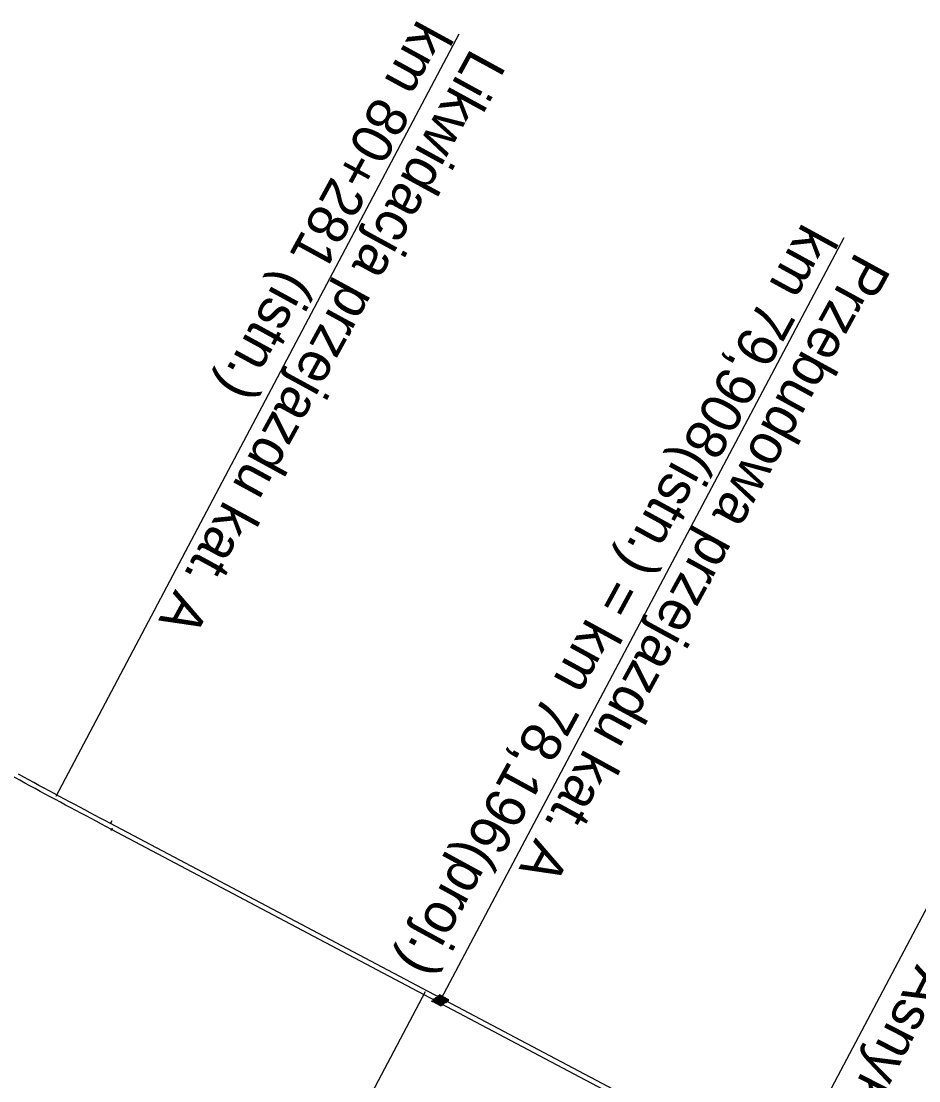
# Model space of a CAD drawing. Extents: x 6540402 to 6566579, y 5525343 to 5532423.
# Drawn here: x 6541266 to 6542041, y 5527285 to 5528200 of the extents above; entities that cross this region are included whole.
import ezdxf

# ---------------------------------------------------------------- set-up
doc = ezdxf.new("R2010")
doc.units = 0
for name, color, linetype in [('IR_ps_geometria', 7, 'Continuous'), ('TOR_PS_OPIS_T-opisy dodatkowe', 7, 'Continuous'), ('TOR_PS_OPIS_T-symbole geometrii', 7, 'Continuous'), ('TOR_PS_P-płyty przejazdowe', 7, 'Continuous'), ('TOR_PS_T-tory projektowane', 7, 'Continuous')]:
    doc.layers.add(name, color=color, linetype=linetype)

msp = doc.modelspace()

# ---------------------------------------------------------------- linework, layer by layer
at = {"layer": 'IR_ps_geometria'}
msp.add_lwpolyline([(6541344.09, 5527502.02), (6541343.97, 5527501.8), (6541344, 5527501.79), (6541344.03, 5527501.76), (6541344.05, 5527501.74), (6541344.07, 5527501.71), (6541344.09, 5527501.69), (6541344.1, 5527501.66), (6541344.1, 5527501.62), (6541344.11, 5527501.59), (6541344.11, 5527501.56), (6541344.1, 5527501.53), (6541344.09, 5527501.49), (6541344.08, 5527501.46), (6541344.06, 5527501.44), (6541344.04, 5527501.41), (6541344.02, 5527501.39), (6541343.99, 5527501.37), (6541343.96, 5527501.35), (6541343.93, 5527501.34), (6541343.9, 5527501.33), (6541343.87, 5527501.33), (6541343.83, 5527501.33), (6541343.8, 5527501.34), (6541343.77, 5527501.35), (6541343.74, 5527501.36), (6541343.71, 5527501.38), (6541343.69, 5527501.4), (6541343.67, 5527501.42), (6541343.65, 5527501.45), (6541343.63, 5527501.48), (6541343.62, 5527501.51), (6541343.61, 5527501.54), (6541343.61, 5527501.57), (6541343.61, 5527501.6), (6541343.61, 5527501.64), (6541343.62, 5527501.67), (6541343.64, 5527501.7), (6541343.65, 5527501.73), (6541343.67, 5527501.75), (6541343.7, 5527501.77), (6541343.73, 5527501.79), (6541343.75, 5527501.81), (6541343.78, 5527501.82), (6541343.82, 5527501.83), (6541343.85, 5527501.83), (6541343.88, 5527501.83), (6541343.91, 5527501.83), (6541343.95, 5527501.82), (6541343.97, 5527501.8), (6541344.21, 5527502.24), (6541344.18, 5527502.26), (6541344.16, 5527502.28), (6541344.13, 5527502.31), (6541344.11, 5527502.33), (6541344.1, 5527502.36), (6541344.09, 5527502.39), (6541344.08, 5527502.42), (6541344.08, 5527502.46), (6541344.08, 5527502.49), (6541344.08, 5527502.52), (6541344.09, 5527502.55), (6541344.1, 5527502.58), (6541344.12, 5527502.61), (6541344.14, 5527502.64), (6541344.17, 5527502.66), (6541344.19, 5527502.68), (6541344.22, 5527502.69), (6541344.25, 5527502.7), (6541344.28, 5527502.71), (6541344.32, 5527502.72), (6541344.35, 5527502.71), (6541344.38, 5527502.71), (6541344.41, 5527502.7), (6541344.44, 5527502.69), (6541344.47, 5527502.67), (6541344.5, 5527502.65), (6541344.52, 5527502.62), (6541344.54, 5527502.6), (6541344.55, 5527502.57), (6541344.56, 5527502.54), (6541344.57, 5527502.51), (6541344.58, 5527502.47), (6541344.57, 5527502.44), (6541344.57, 5527502.41), (6541344.56, 5527502.38), (6541344.55, 5527502.35), (6541344.53, 5527502.32), (6541344.51, 5527502.3), (6541344.48, 5527502.27), (6541344.46, 5527502.25), (6541344.43, 5527502.24), (6541344.4, 5527502.23), (6541344.37, 5527502.22), (6541344.33, 5527502.22), (6541344.3, 5527502.22), (6541344.27, 5527502.22), (6541344.24, 5527502.23), (6541344.21, 5527502.24)], close=True, dxfattribs=at)
msp.add_lwpolyline([(6541344.09, 5527502.02), (6541343.97, 5527501.8), (6541344, 5527501.79), (6541344.03, 5527501.76), (6541344.05, 5527501.74), (6541344.07, 5527501.71), (6541344.09, 5527501.69), (6541344.1, 5527501.66), (6541344.1, 5527501.62), (6541344.11, 5527501.59), (6541344.11, 5527501.56), (6541344.1, 5527501.53), (6541344.09, 5527501.49), (6541344.08, 5527501.46), (6541344.06, 5527501.44), (6541344.04, 5527501.41), (6541344.02, 5527501.39), (6541343.99, 5527501.37), (6541343.96, 5527501.35), (6541343.93, 5527501.34), (6541343.9, 5527501.33), (6541343.87, 5527501.33), (6541343.83, 5527501.33), (6541343.8, 5527501.34), (6541343.77, 5527501.35), (6541343.74, 5527501.36), (6541343.71, 5527501.38), (6541343.69, 5527501.4), (6541343.67, 5527501.42), (6541343.65, 5527501.45), (6541343.63, 5527501.48), (6541343.62, 5527501.51), (6541343.61, 5527501.54), (6541343.61, 5527501.57), (6541343.61, 5527501.6), (6541343.61, 5527501.64), (6541343.62, 5527501.67), (6541343.64, 5527501.7), (6541343.65, 5527501.73), (6541343.67, 5527501.75), (6541343.7, 5527501.77), (6541343.73, 5527501.79), (6541343.75, 5527501.81), (6541343.78, 5527501.82), (6541343.82, 5527501.83), (6541343.85, 5527501.83), (6541343.88, 5527501.83), (6541343.91, 5527501.83), (6541343.95, 5527501.82), (6541343.97, 5527501.8), (6541344.21, 5527502.24), (6541344.18, 5527502.26), (6541344.16, 5527502.28), (6541344.13, 5527502.31), (6541344.11, 5527502.33), (6541344.1, 5527502.36), (6541344.09, 5527502.39), (6541344.08, 5527502.42), (6541344.08, 5527502.46), (6541344.08, 5527502.49), (6541344.08, 5527502.52), (6541344.09, 5527502.55), (6541344.1, 5527502.58), (6541344.12, 5527502.61), (6541344.14, 5527502.64), (6541344.17, 5527502.66), (6541344.19, 5527502.68), (6541344.22, 5527502.69), (6541344.25, 5527502.7), (6541344.28, 5527502.71), (6541344.32, 5527502.72), (6541344.35, 5527502.71), (6541344.38, 5527502.71), (6541344.41, 5527502.7), (6541344.44, 5527502.69), (6541344.47, 5527502.67), (6541344.5, 5527502.65), (6541344.52, 5527502.62), (6541344.54, 5527502.6), (6541344.55, 5527502.57), (6541344.56, 5527502.54), (6541344.57, 5527502.51), (6541344.58, 5527502.47), (6541344.57, 5527502.44), (6541344.57, 5527502.41), (6541344.56, 5527502.38), (6541344.55, 5527502.35), (6541344.53, 5527502.32), (6541344.51, 5527502.3), (6541344.48, 5527502.27), (6541344.46, 5527502.25), (6541344.43, 5527502.24), (6541344.4, 5527502.23), (6541344.37, 5527502.22), (6541344.33, 5527502.22), (6541344.3, 5527502.22), (6541344.27, 5527502.22), (6541344.24, 5527502.23), (6541344.21, 5527502.24)], close=True, dxfattribs=at)
msp.add_lwpolyline([(6541344.09, 5527502.02), (6541343.97, 5527501.8), (6541344, 5527501.79), (6541344.03, 5527501.76), (6541344.05, 5527501.74), (6541344.07, 5527501.71), (6541344.09, 5527501.69), (6541344.1, 5527501.66), (6541344.1, 5527501.62), (6541344.11, 5527501.59), (6541344.11, 5527501.56), (6541344.1, 5527501.53), (6541344.09, 5527501.49), (6541344.08, 5527501.46), (6541344.06, 5527501.44), (6541344.04, 5527501.41), (6541344.02, 5527501.39), (6541343.99, 5527501.37), (6541343.96, 5527501.35), (6541343.93, 5527501.34), (6541343.9, 5527501.33), (6541343.87, 5527501.33), (6541343.83, 5527501.33), (6541343.8, 5527501.34), (6541343.77, 5527501.35), (6541343.74, 5527501.36), (6541343.71, 5527501.38), (6541343.69, 5527501.4), (6541343.67, 5527501.42), (6541343.65, 5527501.45), (6541343.63, 5527501.48), (6541343.62, 5527501.51), (6541343.61, 5527501.54), (6541343.61, 5527501.57), (6541343.61, 5527501.6), (6541343.61, 5527501.64), (6541343.62, 5527501.67), (6541343.64, 5527501.7), (6541343.65, 5527501.73), (6541343.67, 5527501.75), (6541343.7, 5527501.77), (6541343.73, 5527501.79), (6541343.75, 5527501.81), (6541343.78, 5527501.82), (6541343.82, 5527501.83), (6541343.85, 5527501.83), (6541343.88, 5527501.83), (6541343.91, 5527501.83), (6541343.95, 5527501.82), (6541343.97, 5527501.8), (6541344.21, 5527502.24), (6541344.18, 5527502.26), (6541344.16, 5527502.28), (6541344.13, 5527502.31), (6541344.11, 5527502.33), (6541344.1, 5527502.36), (6541344.09, 5527502.39), (6541344.08, 5527502.42), (6541344.08, 5527502.46), (6541344.08, 5527502.49), (6541344.08, 5527502.52), (6541344.09, 5527502.55), (6541344.1, 5527502.58), (6541344.12, 5527502.61), (6541344.14, 5527502.64), (6541344.17, 5527502.66), (6541344.19, 5527502.68), (6541344.22, 5527502.69), (6541344.25, 5527502.7), (6541344.28, 5527502.71), (6541344.32, 5527502.72), (6541344.35, 5527502.71), (6541344.38, 5527502.71), (6541344.41, 5527502.7), (6541344.44, 5527502.69), (6541344.47, 5527502.67), (6541344.5, 5527502.65), (6541344.52, 5527502.62), (6541344.54, 5527502.6), (6541344.55, 5527502.57), (6541344.56, 5527502.54), (6541344.57, 5527502.51), (6541344.58, 5527502.47), (6541344.57, 5527502.44), (6541344.57, 5527502.41), (6541344.56, 5527502.38), (6541344.55, 5527502.35), (6541344.53, 5527502.32), (6541344.51, 5527502.3), (6541344.48, 5527502.27), (6541344.46, 5527502.25), (6541344.43, 5527502.24), (6541344.4, 5527502.23), (6541344.37, 5527502.22), (6541344.33, 5527502.22), (6541344.3, 5527502.22), (6541344.27, 5527502.22), (6541344.24, 5527502.23), (6541344.21, 5527502.24)], close=True, dxfattribs=at)
msp.add_lwpolyline([(6541344.09, 5527502.02), (6541343.97, 5527501.8), (6541344, 5527501.79), (6541344.03, 5527501.76), (6541344.05, 5527501.74), (6541344.07, 5527501.71), (6541344.09, 5527501.69), (6541344.1, 5527501.66), (6541344.1, 5527501.62), (6541344.11, 5527501.59), (6541344.11, 5527501.56), (6541344.1, 5527501.53), (6541344.09, 5527501.49), (6541344.08, 5527501.46), (6541344.06, 5527501.44), (6541344.04, 5527501.41), (6541344.02, 5527501.39), (6541343.99, 5527501.37), (6541343.96, 5527501.35), (6541343.93, 5527501.34), (6541343.9, 5527501.33), (6541343.87, 5527501.33), (6541343.83, 5527501.33), (6541343.8, 5527501.34), (6541343.77, 5527501.35), (6541343.74, 5527501.36), (6541343.71, 5527501.38), (6541343.69, 5527501.4), (6541343.67, 5527501.42), (6541343.65, 5527501.45), (6541343.63, 5527501.48), (6541343.62, 5527501.51), (6541343.61, 5527501.54), (6541343.61, 5527501.57), (6541343.61, 5527501.6), (6541343.61, 5527501.64), (6541343.62, 5527501.67), (6541343.64, 5527501.7), (6541343.65, 5527501.73), (6541343.67, 5527501.75), (6541343.7, 5527501.77), (6541343.73, 5527501.79), (6541343.75, 5527501.81), (6541343.78, 5527501.82), (6541343.82, 5527501.83), (6541343.85, 5527501.83), (6541343.88, 5527501.83), (6541343.91, 5527501.83), (6541343.95, 5527501.82), (6541343.97, 5527501.8), (6541344.21, 5527502.24), (6541344.18, 5527502.26), (6541344.16, 5527502.28), (6541344.13, 5527502.31), (6541344.11, 5527502.33), (6541344.1, 5527502.36), (6541344.09, 5527502.39), (6541344.08, 5527502.42), (6541344.08, 5527502.46), (6541344.08, 5527502.49), (6541344.08, 5527502.52), (6541344.09, 5527502.55), (6541344.1, 5527502.58), (6541344.12, 5527502.61), (6541344.14, 5527502.64), (6541344.17, 5527502.66), (6541344.19, 5527502.68), (6541344.22, 5527502.69), (6541344.25, 5527502.7), (6541344.28, 5527502.71), (6541344.32, 5527502.72), (6541344.35, 5527502.71), (6541344.38, 5527502.71), (6541344.41, 5527502.7), (6541344.44, 5527502.69), (6541344.47, 5527502.67), (6541344.5, 5527502.65), (6541344.52, 5527502.62), (6541344.54, 5527502.6), (6541344.55, 5527502.57), (6541344.56, 5527502.54), (6541344.57, 5527502.51), (6541344.58, 5527502.47), (6541344.57, 5527502.44), (6541344.57, 5527502.41), (6541344.56, 5527502.38), (6541344.55, 5527502.35), (6541344.53, 5527502.32), (6541344.51, 5527502.3), (6541344.48, 5527502.27), (6541344.46, 5527502.25), (6541344.43, 5527502.24), (6541344.4, 5527502.23), (6541344.37, 5527502.22), (6541344.33, 5527502.22), (6541344.3, 5527502.22), (6541344.27, 5527502.22), (6541344.24, 5527502.23), (6541344.21, 5527502.24)], close=True, dxfattribs=at)
at = {"layer": 'TOR_PS_OPIS_T-opisy dodatkowe'}
for p, q in [((6541644.03, 5528189.07), (6541295.77, 5527530.49)), ((6541976.51, 5528013.26), (6541628.25, 5527354.67)), ((6542271.75, 5527857.13), (6541923.49, 5527198.55)), ((6541614.99, 5527361.68), (6541266.73, 5526703.1))]:
    msp.add_line(p, q, dxfattribs=at)
at = {"layer": 'TOR_PS_OPIS_T-symbole geometrii'}
for q in [(6541343.05, 5527508.14), (6541344.48, 5527509.79), (6541343.93, 5527507.67)]:
    msp.add_line((6541343.08, 5527507.14), q, dxfattribs=at)
at = {"layer": 'TOR_PS_P-płyty przejazdowe'}
msp.add_line((6541627.91, 5527354.26), (6541627.93, 5527354.19), dxfattribs=at)
for points in [[(6541626.11, 5527356.74), (6541626.72, 5527357.89), (6541626.19, 5527358.17), (6541625.58, 5527357.02)], [(6541626.64, 5527356.46), (6541627.25, 5527357.6), (6541626.72, 5527357.89), (6541626.11, 5527356.74)], [(6541627.17, 5527356.18), (6541627.78, 5527357.32), (6541627.25, 5527357.6), (6541626.64, 5527356.46)], [(6541627.32, 5527357.74), (6541627.88, 5527358.8), (6541627.35, 5527359.08), (6541626.79, 5527358.02)], [(6541627.85, 5527357.46), (6541628.41, 5527358.52), (6541627.88, 5527358.8), (6541627.32, 5527357.74)], [(6541628.38, 5527357.18), (6541628.94, 5527358.24), (6541628.41, 5527358.52), (6541627.85, 5527357.46)], [(6541628.91, 5527356.9), (6541629.47, 5527357.96), (6541628.94, 5527358.24), (6541628.38, 5527357.18)], [(6541629.44, 5527356.62), (6541630, 5527357.68), (6541629.47, 5527357.96), (6541628.91, 5527356.9)], [(6541629.97, 5527356.33), (6541630.53, 5527357.4), (6541630, 5527357.68), (6541629.44, 5527356.62)], [(6541630.5, 5527356.05), (6541631.06, 5527357.12), (6541630.53, 5527357.4), (6541629.97, 5527356.33)], [(6541621.85, 5527354.24), (6541621.29, 5527353.18), (6541620.76, 5527353.46), (6541621.32, 5527354.52)], [(6541622.38, 5527353.96), (6541621.82, 5527352.9), (6541621.29, 5527353.18), (6541621.85, 5527354.24)], [(6541622.91, 5527353.68), (6541622.35, 5527352.62), (6541621.82, 5527352.9), (6541622.38, 5527353.96)], [(6541622.45, 5527354.09), (6541623.06, 5527355.24), (6541622.53, 5527355.52), (6541621.92, 5527354.37)], [(6541623.44, 5527353.4), (6541622.88, 5527352.34), (6541622.35, 5527352.62), (6541622.91, 5527353.68)], [(6541622.98, 5527353.81), (6541623.59, 5527354.96), (6541623.06, 5527355.24), (6541622.45, 5527354.09)], [(6541623.97, 5527353.12), (6541623.41, 5527352.06), (6541622.88, 5527352.34), (6541623.44, 5527353.4)], [(6541623.51, 5527353.53), (6541624.12, 5527354.68), (6541623.59, 5527354.96), (6541622.98, 5527353.81)], [(6541623.66, 5527355.09), (6541624.22, 5527356.15), (6541623.69, 5527356.43), (6541623.13, 5527355.37)], [(6541624.5, 5527352.84), (6541623.94, 5527351.78), (6541623.41, 5527352.06), (6541623.97, 5527353.12)], [(6541624.04, 5527353.25), (6541624.65, 5527354.4), (6541624.12, 5527354.68), (6541623.51, 5527353.53)], [(6541624.19, 5527354.81), (6541624.75, 5527355.87), (6541624.22, 5527356.15), (6541623.66, 5527355.09)], [(6541625.03, 5527352.56), (6541624.47, 5527351.5), (6541623.94, 5527351.78), (6541624.5, 5527352.84)], [(6541624.57, 5527352.97), (6541625.18, 5527354.12), (6541624.65, 5527354.4), (6541624.04, 5527353.25)], [(6541624.72, 5527354.53), (6541625.28, 5527355.59), (6541624.75, 5527355.87), (6541624.19, 5527354.81)], [(6541625.51, 5527356.88), (6541624.95, 5527355.82), (6541624.42, 5527356.1), (6541624.98, 5527357.16)], [(6541625.56, 5527352.28), (6541625, 5527351.22), (6541624.47, 5527351.5), (6541625.03, 5527352.56)], [(6541625.1, 5527352.69), (6541625.71, 5527353.84), (6541625.18, 5527354.12), (6541624.57, 5527352.97)], [(6541625.25, 5527354.25), (6541625.81, 5527355.31), (6541625.28, 5527355.59), (6541624.72, 5527354.53)], [(6541626.04, 5527356.6), (6541625.48, 5527355.54), (6541624.95, 5527355.82), (6541625.51, 5527356.88)], [(6541626.09, 5527352), (6541625.53, 5527350.93), (6541625, 5527351.22), (6541625.56, 5527352.28)], [(6541625.63, 5527352.41), (6541626.24, 5527353.56), (6541625.71, 5527353.84), (6541625.1, 5527352.69)], [(6541625.78, 5527353.97), (6541626.34, 5527355.03), (6541625.81, 5527355.31), (6541625.25, 5527354.25)], [(6541626.57, 5527356.32), (6541626.01, 5527355.26), (6541625.48, 5527355.54), (6541626.04, 5527356.6)], [(6541626.62, 5527351.72), (6541626.06, 5527350.65), (6541625.53, 5527350.93), (6541626.09, 5527352)], [(6541626.16, 5527352.13), (6541626.77, 5527353.28), (6541626.24, 5527353.56), (6541625.63, 5527352.41)], [(6541626.31, 5527353.69), (6541626.87, 5527354.75), (6541626.34, 5527355.03), (6541625.78, 5527353.97)], [(6541627.1, 5527356.04), (6541626.54, 5527354.98), (6541626.01, 5527355.26), (6541626.57, 5527356.32)], [(6541627.15, 5527351.43), (6541626.59, 5527350.37), (6541626.06, 5527350.65), (6541626.62, 5527351.72)], [(6541626.69, 5527351.85), (6541627.3, 5527353), (6541626.77, 5527353.28), (6541626.16, 5527352.13)], [(6541626.84, 5527353.41), (6541627.4, 5527354.47), (6541626.87, 5527354.75), (6541626.31, 5527353.69)], [(6541627.63, 5527355.76), (6541627.07, 5527354.7), (6541626.54, 5527354.98), (6541627.1, 5527356.04)], [(6541627.68, 5527351.15), (6541627.12, 5527350.09), (6541626.59, 5527350.37), (6541627.15, 5527351.43)], [(6541627.22, 5527351.57), (6541627.83, 5527352.72), (6541627.3, 5527353), (6541626.69, 5527351.85)], [(6541627.37, 5527353.13), (6541627.93, 5527354.19), (6541627.4, 5527354.47), (6541626.84, 5527353.41)], [(6541628.16, 5527355.48), (6541627.6, 5527354.42), (6541627.07, 5527354.7), (6541627.63, 5527355.76)], [(6541628.21, 5527350.87), (6541627.65, 5527349.81), (6541627.12, 5527350.09), (6541627.68, 5527351.15)], [(6541627.7, 5527355.89), (6541628.31, 5527357.04), (6541627.78, 5527357.32), (6541627.17, 5527356.18)], [(6541627.75, 5527351.29), (6541628.36, 5527352.44), (6541627.83, 5527352.72), (6541627.22, 5527351.57)], [(6541627.9, 5527352.85), (6541628.46, 5527353.91), (6541627.93, 5527354.19), (6541627.37, 5527353.13)], [(6541628.69, 5527355.2), (6541628.13, 5527354.14), (6541627.6, 5527354.42), (6541628.16, 5527355.48)], [(6541628.74, 5527350.59), (6541628.18, 5527349.53), (6541627.65, 5527349.81), (6541628.21, 5527350.87)], [(6541628.23, 5527355.61), (6541628.84, 5527356.76), (6541628.31, 5527357.04), (6541627.7, 5527355.89)], [(6541628.28, 5527351.01), (6541628.89, 5527352.16), (6541628.36, 5527352.44), (6541627.75, 5527351.29)], [(6541628.43, 5527352.57), (6541628.99, 5527353.63), (6541628.46, 5527353.91), (6541627.9, 5527352.85)], [(6541629.22, 5527354.92), (6541628.66, 5527353.86), (6541628.13, 5527354.14), (6541628.69, 5527355.2)], [(6541629.27, 5527350.31), (6541628.71, 5527349.25), (6541628.18, 5527349.53), (6541628.74, 5527350.59)], [(6541628.76, 5527355.33), (6541629.37, 5527356.48), (6541628.84, 5527356.76), (6541628.23, 5527355.61)], [(6541628.81, 5527350.73), (6541629.42, 5527351.88), (6541628.89, 5527352.16), (6541628.28, 5527351.01)], [(6541628.96, 5527352.29), (6541629.52, 5527353.35), (6541628.99, 5527353.63), (6541628.43, 5527352.57)], [(6541629.76, 5527354.64), (6541629.19, 5527353.58), (6541628.66, 5527353.86), (6541629.22, 5527354.92)], [(6541629.29, 5527355.05), (6541629.9, 5527356.2), (6541629.37, 5527356.48), (6541628.76, 5527355.33)], [(6541629.34, 5527350.45), (6541629.95, 5527351.59), (6541629.42, 5527351.88), (6541628.81, 5527350.73)], [(6541629.49, 5527352.01), (6541630.05, 5527353.07), (6541629.52, 5527353.35), (6541628.96, 5527352.29)], [(6541630.29, 5527354.36), (6541629.72, 5527353.3), (6541629.19, 5527353.58), (6541629.76, 5527354.64)], [(6541629.83, 5527354.77), (6541630.43, 5527355.92), (6541629.9, 5527356.2), (6541629.29, 5527355.05)], [(6541629.88, 5527350.16), (6541630.48, 5527351.31), (6541629.95, 5527351.59), (6541629.34, 5527350.45)], [(6541630.02, 5527351.73), (6541630.58, 5527352.79), (6541630.05, 5527353.07), (6541629.49, 5527352.01)], [(6541630.82, 5527354.08), (6541630.26, 5527353.02), (6541629.72, 5527353.3), (6541630.29, 5527354.36)], [(6541630.36, 5527354.49), (6541630.96, 5527355.64), (6541630.43, 5527355.92), (6541629.83, 5527354.77)], [(6541630.55, 5527351.45), (6541631.11, 5527352.51), (6541630.58, 5527352.79), (6541630.02, 5527351.73)], [(6541631.35, 5527353.8), (6541630.79, 5527352.74), (6541630.26, 5527353.02), (6541630.82, 5527354.08)], [(6541630.89, 5527354.21), (6541631.49, 5527355.36), (6541630.96, 5527355.64), (6541630.36, 5527354.49)], [(6541631.03, 5527355.77), (6541631.59, 5527356.83), (6541631.06, 5527357.12), (6541630.5, 5527356.05)], [(6541631.08, 5527351.17), (6541631.64, 5527352.23), (6541631.11, 5527352.51), (6541630.55, 5527351.45)], [(6541631.88, 5527353.52), (6541631.32, 5527352.46), (6541630.79, 5527352.74), (6541631.35, 5527353.8)], [(6541631.42, 5527353.93), (6541632.02, 5527355.08), (6541631.49, 5527355.36), (6541630.89, 5527354.21)], [(6541631.56, 5527355.49), (6541632.12, 5527356.55), (6541631.59, 5527356.83), (6541631.03, 5527355.77)], [(6541632.41, 5527353.24), (6541631.85, 5527352.18), (6541631.32, 5527352.46), (6541631.88, 5527353.52)], [(6541631.95, 5527353.65), (6541632.55, 5527354.8), (6541632.02, 5527355.08), (6541631.42, 5527353.93)], [(6541632.09, 5527355.21), (6541632.66, 5527356.27), (6541632.12, 5527356.55), (6541631.56, 5527355.49)], [(6541632.94, 5527352.96), (6541632.38, 5527351.9), (6541631.85, 5527352.18), (6541632.41, 5527353.24)], [(6541632.48, 5527353.37), (6541633.09, 5527354.52), (6541632.55, 5527354.8), (6541631.95, 5527353.65)], [(6541632.62, 5527354.93), (6541633.19, 5527355.99), (6541632.66, 5527356.27), (6541632.09, 5527355.21)], [(6541633.01, 5527353.09), (6541633.62, 5527354.24), (6541633.09, 5527354.52), (6541632.48, 5527353.37)], [(6541633.16, 5527354.65), (6541633.72, 5527355.71), (6541633.19, 5527355.99), (6541632.62, 5527354.93)], [(6541633.54, 5527352.81), (6541634.15, 5527353.96), (6541633.62, 5527354.24), (6541633.01, 5527353.09)], [(6541633.69, 5527354.37), (6541634.25, 5527355.43), (6541633.72, 5527355.71), (6541633.16, 5527354.65)], [(6541634.22, 5527354.09), (6541634.78, 5527355.15), (6541634.25, 5527355.43), (6541633.69, 5527354.37)], [(6541634.75, 5527353.81), (6541635.31, 5527354.87), (6541634.78, 5527355.15), (6541634.22, 5527354.09)]]:
    msp.add_lwpolyline(points, close=True, dxfattribs=at)
at = {"layer": 'TOR_PS_T-tory projektowane'}
for p, q in [((6542564.4, 5526861.3), (6541343.08, 5527507.14)), ((6542565.68, 5526856.05), (6541344.09, 5527502.02))]:
    msp.add_line(p, q, dxfattribs=at)
for points in [[(6541344.09, 5527502.02), (6541339.67, 5527504.36), (6541335.25, 5527506.7), (6541330.83, 5527509.04), (6541326.41, 5527511.38), (6541322, 5527513.72), (6541317.58, 5527516.06), (6541313.16, 5527518.41), (6541308.75, 5527520.75), (6541304.34, 5527523.11), (6541299.92, 5527525.46), (6541295.52, 5527527.82), (6541291.11, 5527530.18), (6541286.7, 5527532.55), (6541282.3, 5527534.92), (6541277.9, 5527537.3), (6541273.51, 5527539.68), (6541269.12, 5527542.07), (6541264.73, 5527544.46), (6541260.34, 5527546.86), (6541255.96, 5527549.27)], [(6541343.08, 5527507.14), (6541338.66, 5527509.48), (6541334.24, 5527511.81), (6541329.82, 5527514.15), (6541325.4, 5527516.49), (6541320.99, 5527518.83), (6541316.57, 5527521.18), (6541312.15, 5527523.52), (6541307.74, 5527525.87), (6541303.33, 5527528.23), (6541298.92, 5527530.58), (6541294.51, 5527532.94), (6541290.11, 5527535.31), (6541285.7, 5527537.68), (6541281.3, 5527540.05), (6541276.91, 5527542.43), (6541272.51, 5527544.82), (6541268.12, 5527547.22), (6541263.74, 5527549.62)]]:
    msp.add_lwpolyline(points, dxfattribs=at)

# ---------------------------------------------------------------- texts
at = {"layer": 'TOR_PS_OPIS_T-opisy dodatkowe'}
for s, rotation, p in [('km 80+281 (istn.)', 241.35666, (6541608.68, 5528203.16)), ('Likwidacja przejazdu kat. A', 241.35666, (6541654.75, 5528178)), ('km 79,908(istn.) = km 78,196(proj.)', 241.35666, (6541941.16, 5528027.35)), ('Przebudowa przejazdu kat. A', 241.35666, (6541987.23, 5528002.18)), ('Wiadukt kolejowy nad ul. Asnyka (boczna)', 242.8298, (6542280.87, 5527855.96))]:
    msp.add_text(s, height=35, rotation=rotation, dxfattribs=at).set_placement(p)

doc.saveas('drawing.dxf')
